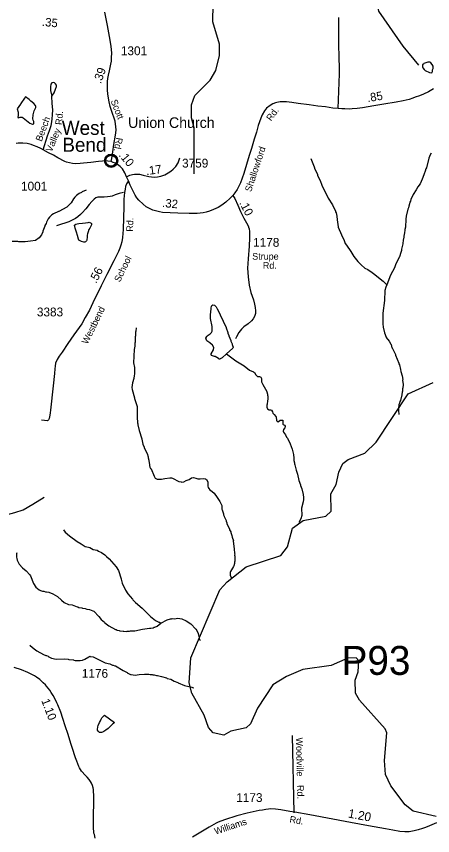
# Model space of a CAD drawing. Extents: x 1547597 to 1699558, y 810033 to 920809.
# Drawn here: x 1558854 to 1564751, y 847304 to 858918 of the extents above; entities that cross this region are included whole.
import ezdxf

# ---------------------------------------------------------------- set-up
doc = ezdxf.new("R2010")
doc.units = 0
for name, color, linetype in [('Exist Civil Demographics Community CELL', 7, 'Continuous'), ('Exist Civil Demographics Community Label', 7, 'Continuous'), ('Exist Cultural Church with Cemetery Label', 7, 'Continuous'), ('Exist Hydrographic Creek Single Shore', 7, 'Continuous'), ('Exist Hydrographic Misc Water Feature', 7, 'Continuous'), ('Exist Road Non-System Type 51', 7, 'Continuous'), ('Exist Road Non-System Type 51 Label', 7, 'Continuous'), ('Exist Road Secondary Mileage Hundredths English Label', 7, 'Continuous'), ('Exist Road Secondary Structure Pipe Number Label', 7, 'Continuous'), ('Exist Road Secondary Type 41 Attributed', 7, 'Continuous'), ('Exist Road Secondary Type 51 Attributed', 7, 'Continuous'), ('Exist Road Secondary Type 51 Label', 7, 'Continuous'), ('Exist Road Secondary Type 51 Number Label', 7, 'Continuous')]:
    doc.layers.add(name, color=color, linetype=linetype)

msp = doc.modelspace()

# ---------------------------------------------------------------- linework, layer by layer
at = {"layer": 'Exist Civil Demographics Community CELL'}
msp.add_lwpolyline([(1560119, 856884), (1560120, 856890), (1560121, 856896), (1560124, 856904), (1560127, 856909), (1560131, 856915), (1560134, 856920), (1560138, 856925), (1560143, 856929), (1560148, 856934), (1560154, 856937), (1560159, 856940), (1560164, 856943), (1560169, 856945), (1560175, 856947), (1560179, 856948), (1560184, 856949), (1560188, 856949), (1560195, 856950), (1560199, 856950), (1560205, 856949), (1560210, 856949), (1560214, 856948), (1560219, 856946), (1560225, 856944), (1560231, 856941), (1560237, 856938), (1560243, 856934), (1560248, 856930), (1560251, 856927), (1560255, 856923), (1560259, 856918), (1560262, 856913), (1560265, 856908), (1560268, 856903), (1560270, 856898), (1560271, 856893), (1560273, 856889), (1560274, 856883), (1560274, 856878), (1560275, 856872), (1560274, 856866), (1560274, 856860), (1560273, 856855), (1560271, 856849), (1560269, 856843), (1560267, 856838), (1560264, 856832), (1560261, 856827), (1560257, 856822), (1560253, 856817), (1560248, 856812), (1560243, 856808), (1560238, 856805), (1560233, 856802), (1560226, 856799), (1560219, 856796), (1560213, 856795), (1560207, 856793), (1560202, 856793), (1560198, 856793), (1560192, 856793), (1560188, 856793), (1560182, 856794), (1560176, 856795), (1560172, 856796), (1560167, 856798), (1560162, 856800), (1560158, 856803), (1560151, 856807), (1560146, 856811), (1560141, 856815), (1560136, 856820), (1560133, 856824), (1560130, 856828), (1560126, 856835), (1560124, 856839), (1560123, 856843), (1560120, 856851), (1560119, 856858), (1560118, 856863), (1560118, 856870), (1560118, 856874), (1560118, 856881)], close=True, dxfattribs=at)
for radius in [94.3, 76.7]:
    msp.add_circle((1560196, 856872), radius, dxfattribs=at)
at = {"layer": 'Exist Hydrographic Creek Single Shore'}
msp.add_lwpolyline([(1564801, 847575), (1564477, 847653), (1564361, 847741), (1564157, 848008), (1564084, 848170), (1564070, 848368), (1564101, 848761), (1564077, 848820), (1563716, 849225), (1563659, 849325), (1563653, 849509), (1563697, 849626), (1563707, 849783), (1563666, 849827), (1563549, 849819), (1563315, 849716), (1562914, 849661), (1562679, 849558), (1562485, 849444), (1562272, 849113), (1562169, 848889), (1562109, 848831), (1561892, 848783), (1561791, 848729), (1561642, 848761), (1561576, 848838), (1561512, 849014), (1561341, 849326), (1561302, 849468), (1561324, 849825), (1561738, 850788), (1561839, 850901), (1562109, 851116), (1562603, 851276), (1562697, 851399), (1562767, 851664), (1562919, 851772), (1563237, 851831), (1563313, 851905), (1563308, 852148), (1563385, 852281), (1563421, 852455), (1563481, 852578), (1563557, 852636), (1563792, 852726), (1563952, 852880), (1564404, 853567), (1564757, 853728)], dxfattribs=at)
at = {"layer": 'Exist Hydrographic Misc Water Feature'}
for points in [[(1561373, 856688), (1561374, 857338), (1561334, 857480), (1561337, 857664), (1561381, 857798), (1561601, 858016), (1561678, 858149), (1561731, 858365), (1561733, 858526), (1561638, 858843), (1561645, 859342), (1561700, 859725), (1561669, 859866), (1561472, 860081), (1561440, 860147), (1561443, 860354), (1561495, 860504), (1561382, 860782), (1561361, 861015), (1561375, 861432), (1561254, 861733), (1561273, 861900)], [(1564555, 858226), (1564334, 858496), (1563991, 858992), (1563920, 859286), (1563875, 859661), (1563811, 859787), (1563630, 859965), (1563107, 860156), (1562951, 860284), (1562788, 860543), (1562759, 860895), (1562694, 860995), (1562554, 861122), (1562347, 861225), (1562232, 861326), (1562091, 861388), (1561867, 861425), (1561701, 861501), (1561348, 861882), (1561273, 861900)], [(1564608, 858238), (1564608, 858204), (1564612, 858188), (1564630, 858164), (1564647, 858151), (1564707, 858123), (1564739, 858120), (1564751, 858138), (1564751, 858162), (1564760, 858178), (1564760, 858210), (1564746, 858234), (1564725, 858260), (1564713, 858269), (1564685, 858267), (1564653, 858259), (1564628, 858248), (1564622, 858240), (1564608, 858238)], [(1558917, 857682), (1558915, 857680), (1558911, 857672), (1558866, 857608), (1558877, 857560), (1558877, 857512), (1558873, 857488), (1558879, 857480), (1558909, 857488), (1558933, 857488), (1558948, 857479), (1559044, 857406), (1559067, 857394), (1559083, 857390), (1559091, 857390), (1559103, 857399), (1559100, 857429), (1559092, 857446), (1559088, 857468), (1559089, 857522), (1559104, 857577), (1559130, 857625), (1559130, 857641), (1559123, 857657), (1559099, 857683), (1559059, 857716), (1559035, 857740), (1558983, 857779), (1558968, 857757), (1558917, 857682)], [(1564733, 856979), (1564713, 856947), (1564709, 856931), (1564697, 856907), (1564663, 856772), (1564655, 856756), (1564646, 856724), (1564630, 856684), (1564628, 856673), (1564605, 856609), (1564576, 856545), (1564543, 856504), (1564519, 856458), (1564474, 856394), (1564442, 856323), (1564437, 856299), (1564429, 856283), (1564425, 856259), (1564413, 856227), (1564408, 856203), (1564400, 856187), (1564378, 856086), (1564370, 856044), (1564365, 855928), (1564357, 855896), (1564352, 855840), (1564348, 855832), (1564339, 855760), (1564335, 855752), (1564330, 855696), (1564309, 855617), (1564309, 855601), (1564299, 855573), (1564284, 855509), (1564279, 855505), (1564226, 855396), (1564210, 855354), (1564153, 855251), (1564101, 855114)], [(1563024, 856903), (1563075, 856784), (1563083, 856752), (1563118, 856679), (1563122, 856663), (1563159, 856591), (1563180, 856527), (1563270, 856342), (1563333, 856245), (1563376, 856156), (1563376, 856148), (1563384, 856132), (1563395, 856084), (1563398, 856036), (1563415, 855936), (1563413, 855932), (1563460, 855819), (1563496, 855739), (1563514, 855699), (1563530, 855675), (1563593, 855586), (1563636, 855513), (1563691, 855441), (1563739, 855394), (1563790, 855351), (1563834, 855330), (1563897, 855288), (1563913, 855272), (1564052, 855164), (1564101, 855114)], [(1559840, 856455), (1559784, 856429), (1559778, 856423), (1559744, 856406), (1559705, 856378), (1559681, 856355), (1559663, 856331), (1559628, 856275), (1559569, 856212), (1559457, 856154), (1559451, 856153), (1559378, 856121), (1559354, 856103), (1559322, 856071), (1559303, 856048), (1559279, 856000), (1559275, 855984), (1559258, 855952), (1559258, 855944), (1559229, 855873), (1559229, 855865), (1559207, 855819), (1559176, 855777), (1559124, 855742), (1559052, 855731), (1558976, 855724), (1558928, 855724), (1558912, 855721), (1558888, 855721), (1558872, 855725), (1558792, 855726)], [(1559739, 855981), (1559790, 855987), (1559834, 855992), (1559871, 855998), (1559883, 855999), (1559895, 855997), (1559913, 855987), (1559916, 855980), (1559916, 855962), (1559914, 855954), (1559906, 855942), (1559892, 855918), (1559882, 855895), (1559872, 855865), (1559863, 855836), (1559858, 855817), (1559857, 855794), (1559854, 855744), (1559849, 855735), (1559833, 855723), (1559822, 855719), (1559810, 855719), (1559775, 855728), (1559750, 855739), (1559739, 855747), (1559732, 855761), (1559719, 855813), (1559705, 855858), (1559687, 855915), (1559675, 855959), (1559696, 855971), (1559717, 855977), (1559739, 855981)], [(1564101, 855114), (1564087, 855080), (1564076, 855032), (1564069, 854888), (1564047, 854712), (1564044, 854673), (1564045, 854561), (1564050, 854513), (1564069, 854432), (1564095, 854370), (1564095, 854364), (1564134, 854316), (1564160, 854270), (1564165, 854267), (1564173, 854219), (1564179, 854217), (1564224, 854123), (1564224, 854115), (1564274, 854002), (1564274, 853994), (1564282, 853978), (1564297, 853914), (1564301, 853882), (1564320, 853821), (1564329, 853769), (1564327, 853761), (1564335, 853701), (1564330, 853649), (1564326, 853641), (1564325, 853601), (1564321, 853594), (1564317, 853554), (1564296, 853474), (1564288, 853458), (1564283, 853434), (1564275, 853418), (1564271, 853386), (1564267, 853378), (1564266, 853330), (1564273, 853276)], [(1561833, 854132), (1561768, 854079), (1561743, 854062), (1561735, 854060), (1561727, 854060), (1561716, 854070), (1561668, 854095), (1561660, 854095), (1561620, 854111), (1561612, 854123), (1561612, 854135), (1561647, 854191), (1561649, 854223), (1561632, 854255), (1561594, 854289), (1561553, 854320), (1561541, 854340), (1561539, 854356), (1561551, 854380), (1561557, 854388), (1561600, 854417), (1561620, 854439), (1561628, 854455), (1561630, 854479), (1561629, 854523), (1561602, 854635), (1561603, 854707), (1561607, 854715), (1561612, 854787), (1561616, 854803), (1561624, 854819), (1561636, 854829), (1561660, 854826), (1561682, 854802), (1561700, 854774), (1561731, 854710), (1561739, 854685), (1561825, 854509), (1561825, 854501), (1561848, 854436), (1561848, 854428), (1561863, 854396), (1561863, 854388), (1561890, 854324), (1561890, 854316), (1561910, 854276), (1561910, 854268), (1561918, 854251), (1561923, 854227), (1561921, 854213), (1561833, 854132)], [(1560549, 854505), (1560544, 854457), (1560540, 854443), (1560542, 854437), (1560540, 854389), (1560535, 854373), (1560535, 854301), (1560530, 854285), (1560530, 854245), (1560521, 854197), (1560511, 854005), (1560526, 853941), (1560529, 853865), (1560521, 853809), (1560517, 853801), (1560516, 853785), (1560500, 853721), (1560491, 853658), (1560495, 853628), (1560525, 853509), (1560529, 853503), (1560564, 853389), (1560563, 853335), (1560567, 853313), (1560565, 853201), (1560569, 853193), (1560569, 853153), (1560573, 853145), (1560573, 853129), (1560592, 853049), (1560630, 852928), (1560629, 852923), (1560643, 852856), (1560665, 852812), (1560665, 852804), (1560706, 852723), (1560723, 852675), (1560723, 852659), (1560731, 852627), (1560730, 852611), (1560734, 852603), (1560740, 852551), (1560745, 852527), (1560753, 852511), (1560763, 852502), (1560804, 852398), (1560822, 852373), (1560849, 852357), (1560910, 852359), (1560955, 852366), (1561028, 852377), (1561052, 852375), (1561067, 852371), (1561155, 852326), (1561187, 852321), (1561195, 852317), (1561227, 852321), (1561259, 852338), (1561304, 852355), (1561335, 852377), (1561365, 852380), (1561398, 852374), (1561426, 852364), (1561456, 852361), (1561504, 852365), (1561535, 852361), (1561547, 852353), (1561567, 852321), (1561566, 852259), (1561572, 852239), (1561580, 852225), (1561593, 852206), (1561627, 852184), (1561655, 852160), (1561700, 852099), (1561736, 852043), (1561763, 851986), (1561766, 851930), (1561771, 851923), (1561787, 851866), (1561789, 851850), (1561797, 851834), (1561797, 851826), (1561824, 851770), (1561824, 851762), (1561836, 851738), (1561836, 851730), (1561875, 851649), (1561875, 851641), (1561890, 851609), (1561890, 851601), (1561906, 851561), (1561909, 851537), (1561929, 851484), (1561927, 851477), (1561939, 851372), (1561938, 851364), (1561943, 851308), (1561947, 851300), (1561946, 851278)], [(1561833, 854132), (1561963, 854035), (1562080, 853966), (1562157, 853905), (1562211, 853880), (1562227, 853868), (1562245, 853837), (1562264, 853819), (1562272, 853815), (1562296, 853815), (1562318, 853803), (1562328, 853786), (1562328, 853739), (1562345, 853698), (1562402, 853602), (1562402, 853594), (1562413, 853561), (1562413, 853545), (1562417, 853537), (1562416, 853482), (1562412, 853474), (1562408, 853418), (1562404, 853410), (1562403, 853380), (1562409, 853362), (1562413, 853356), (1562435, 853341), (1562455, 853341), (1562469, 853335), (1562482, 853313), (1562486, 853291), (1562506, 853274), (1562530, 853248), (1562533, 853240), (1562539, 853188), (1562547, 853178), (1562561, 853172), (1562593, 853193), (1562629, 853195), (1562630, 853137), (1562636, 853131), (1562654, 853125), (1562664, 853111), (1562664, 853103), (1562656, 853087), (1562637, 853063), (1562635, 853039), (1562639, 853023), (1562666, 852987), (1562682, 852954), (1562694, 852938), (1562733, 852858), (1562760, 852785), (1562779, 852705), (1562783, 852653), (1562786, 852645), (1562786, 852621), (1562794, 852589), (1562794, 852573), (1562799, 852561), (1562817, 852485), (1562836, 852429), (1562855, 852340), (1562878, 852276), (1562878, 852268), (1562897, 852220), (1562916, 852140), (1562916, 852124), (1562920, 852116), (1562922, 852068), (1562919, 852036), (1562894, 851948), (1562897, 851844), (1562884, 851796), (1562856, 851742)], [(1559521, 851639), (1559547, 851608), (1559606, 851556), (1559713, 851474), (1559773, 851442), (1559828, 851403), (1559835, 851404), (1559896, 851390), (1559940, 851362), (1559996, 851349), (1560019, 851339), (1560059, 851316), (1560105, 851283), (1560129, 851259), (1560166, 851229), (1560265, 851116), (1560300, 851061), (1560339, 850945), (1560337, 850938), (1560350, 850881), (1560399, 850784), (1560432, 850734), (1560501, 850655), (1560505, 850647), (1560541, 850610), (1560634, 850529), (1560752, 850410), (1560824, 850355), (1560871, 850330), (1560883, 850328), (1560899, 850318)], [(1558859, 851315), (1558855, 851299), (1558855, 851253), (1558858, 851231), (1558866, 851207), (1558893, 851153), (1558941, 851100), (1558994, 851058), (1559046, 851001), (1559055, 850987), (1559098, 850880), (1559130, 850828), (1559177, 850787), (1559193, 850779), (1559225, 850771), (1559241, 850771), (1559265, 850762), (1559281, 850762), (1559313, 850754), (1559368, 850733), (1559434, 850692), (1559495, 850643), (1559531, 850611), (1559591, 850582), (1559646, 850574), (1559714, 850549), (1559722, 850549), (1559738, 850540), (1559782, 850532), (1559790, 850528), (1559830, 850523), (1559854, 850515), (1559890, 850511), (1559939, 850492), (1559953, 850484), (1560024, 850411), (1560056, 850368), (1560104, 850328), (1560106, 850322), (1560165, 850277), (1560258, 850226), (1560266, 850226), (1560282, 850218), (1560310, 850213), (1560318, 850209), (1560366, 850205), (1560374, 850201), (1560414, 850200), (1560422, 850204), (1560454, 850204), (1560470, 850207), (1560534, 850207), (1560642, 850229), (1560742, 850244), (1560758, 850244), (1560790, 850251), (1560807, 850259), (1560815, 850259), (1560847, 850275), (1560899, 850318)], [(1561946, 851278), (1561950, 851264), (1561949, 851192), (1561945, 851184), (1561945, 851160), (1561933, 851129), (1561932, 851121), (1561888, 851049), (1561883, 851033), (1561883, 850993), (1561900, 850959)], [(1560899, 850318), (1560988, 850361), (1561036, 850376), (1561052, 850376), (1561060, 850380), (1561092, 850379), (1561143, 850388), (1561200, 850378), (1561259, 850349), (1561325, 850305), (1561396, 850232), (1561410, 850212), (1561429, 850171), (1561445, 850107), (1561444, 850091), (1561448, 850083), (1561460, 850077)], [(1559044, 850003), (1559050, 850001), (1559107, 849951), (1559143, 849926), (1559238, 849873), (1559270, 849859), (1559278, 849859), (1559306, 849848), (1559306, 849842), (1559350, 849818), (1559419, 849804), (1559541, 849809), (1559589, 849807), (1559597, 849802), (1559661, 849794), (1559669, 849790), (1559685, 849789), (1559693, 849785), (1559749, 849785), (1559757, 849788), (1559789, 849792), (1559821, 849806), (1559878, 849841), (1559892, 849847), (1559898, 849843), (1559942, 849838), (1560113, 849756), (1560177, 849739), (1560216, 849723), (1560224, 849723), (1560248, 849710), (1560256, 849710), (1560367, 849643), (1560423, 849616), (1560423, 849612), (1560471, 849588), (1560478, 849589), (1560535, 849579), (1560594, 849588), (1560671, 849593), (1560691, 849591), (1560731, 849592), (1560747, 849588), (1560779, 849588), (1560787, 849584), (1560808, 849583), (1560838, 849575), (1560854, 849575), (1560910, 849558), (1560980, 849543), (1560990, 849533), (1561042, 849520), (1561089, 849496), (1561141, 849475), (1561147, 849470), (1561237, 849434), (1561340, 849409), (1561358, 849399), (1561370, 849404)], [(1560102, 849012), (1560242, 848908), (1560228, 848894), (1560216, 848883), (1560204, 848873), (1560177, 848846), (1560153, 848823), (1560120, 848797), (1560094, 848781), (1560075, 848771), (1560060, 848766), (1560044, 848764), (1560033, 848767), (1560020, 848776), (1560010, 848787), (1560005, 848797), (1560004, 848809), (1560006, 848846), (1560013, 848865), (1560033, 848909), (1560043, 848933), (1560055, 848956), (1560065, 848973), (1560078, 848989), (1560102, 849012)]]:
    msp.add_lwpolyline(points, dxfattribs=at)
at = {"layer": 'Exist Road Non-System Type 51'}
msp.add_line((1562788, 847628), (1562766, 848723), dxfattribs=at)
for points in [[(1563415, 857611), (1563430, 858104), (1563430, 858186), (1563428, 858340), (1563424, 858518), (1563424, 858904)], [(1559354, 857789), (1559389, 857836), (1559409, 857884), (1559420, 857922), (1559420, 857944), (1559410, 857964), (1559395, 857976), (1559381, 857980), (1559357, 857975), (1559342, 857959), (1559338, 857921), (1559339, 857867), (1559354, 857789)], [(1559235, 857024), (1559296, 857225), (1559323, 857299), (1559344, 857373), (1559357, 857421), (1559361, 857466), (1559366, 857522), (1559371, 857594), (1559360, 857681), (1559354, 857789)], [(1560371, 856421), (1560310, 856408), (1560254, 856387), (1560210, 856370), (1560180, 856364), (1560146, 856359), (1560095, 856355), (1560043, 856356), (1560009, 856355), (1559981, 856345), (1559957, 856327), (1559921, 856296), (1559884, 856250), (1559837, 856189), (1559784, 856134), (1559762, 856108), (1559725, 856075), (1559691, 856051), (1559634, 856024), (1559598, 856006), (1559542, 855987), (1559494, 855974), (1559423, 855949)], [(1562149, 855918), (1562152, 855909), (1562157, 855863), (1562158, 855779), (1562152, 855659), (1562136, 855483), (1562126, 855348), (1562138, 855225), (1562154, 855109), (1562177, 855002), (1562211, 854900), (1562228, 854836), (1562238, 854790), (1562243, 854746), (1562241, 854707), (1562226, 854664), (1562210, 854632), (1562187, 854602), (1562136, 854559), (1562078, 854516), (1562043, 854486), (1562004, 854435), (1561974, 854377), (1561959, 854348)], [(1559393, 853857), (1559374, 853682), (1559337, 853335), (1559332, 853297), (1559326, 853263), (1559316, 853218), (1559308, 853199), (1559294, 853186), (1559211, 853193)], [(1558475, 851891), (1558622, 851872), (1558726, 851858), (1558831, 851887), (1558950, 851925), (1559087, 852001), (1559249, 852100)]]:
    msp.add_lwpolyline(points, dxfattribs=at)
at = {"layer": 'Exist Road Secondary Type 41 Attributed'}
msp.add_lwpolyline([(1561922, 856381), (1561950, 856334), (1561991, 856242), (1562027, 856153), (1562076, 856059), (1562113, 855992), (1562137, 855950), (1562149, 855918)], dxfattribs=at)
at = {"layer": 'Exist Road Secondary Type 51 Attributed'}
for points in [[(1560196, 856859), (1560204, 856905), (1560220, 856999), (1560236, 857102), (1560258, 857233), (1560266, 857303), (1560264, 857356), (1560260, 857392), (1560253, 857432), (1560203, 857582), (1560184, 857642), (1560170, 857709), (1560151, 857817), (1560146, 857878), (1560143, 857959), (1560146, 857997), (1560150, 858038), (1560160, 858083), (1560173, 858146), (1560192, 858241), (1560199, 858281), (1560203, 858330), (1560205, 858401), (1560198, 858490), (1560184, 858580), (1560164, 858687), (1560143, 858788), (1560105, 858978)], [(1564766, 857891), (1564692, 857850), (1564620, 857815), (1564567, 857793), (1564506, 857771), (1564470, 857758), (1564417, 857741), (1564336, 857722), (1564234, 857704), (1564059, 857674), (1563919, 857649), (1563838, 857635), (1563758, 857622), (1563680, 857614), (1563613, 857607), (1563570, 857605), (1563509, 857606), (1563467, 857608), (1563415, 857611), (1563338, 857619), (1563233, 857634), (1563123, 857646), (1563004, 857663), (1562846, 857683), (1562755, 857695), (1562683, 857705), (1562631, 857707), (1562590, 857706), (1562546, 857698), (1562523, 857692), (1562487, 857677), (1562450, 857657), (1562397, 857615), (1562368, 857580), (1562335, 857521), (1562316, 857475), (1562281, 857372), (1562254, 857279), (1562223, 857178), (1562183, 857047), (1562152, 856944), (1562113, 856817), (1562074, 856693), (1562054, 856625), (1562028, 856559), (1562006, 856510), (1561980, 856464), (1561949, 856418), (1561922, 856381)], [(1560196, 856859), (1560151, 856867), (1560119, 856869), (1560073, 856867), (1560016, 856861), (1559910, 856848), (1559804, 856835), (1559759, 856831), (1559691, 856829), (1559649, 856833), (1559607, 856842), (1559565, 856853), (1559542, 856863), (1559439, 856913), (1559377, 856949), (1559308, 856986), (1559235, 857024), (1559199, 857043), (1559148, 857070), (1559098, 857090), (1559065, 857100), (1559006, 857116), (1558946, 857122), (1558910, 857123), (1558877, 857121), (1558848, 857116)], [(1560414, 856645), (1560388, 856702), (1560356, 856755), (1560322, 856792), (1560287, 856820), (1560257, 856837), (1560227, 856849), (1560196, 856859)], [(1560414, 856645), (1560459, 856669), (1560497, 856677), (1560529, 856680), (1560596, 856680), (1560649, 856669), (1560730, 856647), (1560806, 856641), (1560851, 856644), (1560899, 856653), (1560955, 856673), (1561004, 856698), (1561044, 856725), (1561076, 856753), (1561111, 856792), (1561145, 856842), (1561170, 856911)], [(1560440, 856588), (1560414, 856645)], [(1560440, 856588), (1560412, 856543), (1560399, 856508), (1560395, 856467), (1560386, 856420), (1560378, 856326), (1560376, 856220), (1560372, 856060), (1560367, 855898), (1560356, 855785), (1560347, 855724), (1560335, 855677), (1560320, 855630), (1560300, 855585), (1560232, 855454), (1560137, 855259), (1560054, 855097), (1559937, 854855), (1559888, 854752), (1559829, 854649), (1559779, 854561), (1559668, 854403), (1559584, 854279), (1559500, 854156), (1559461, 854102), (1559430, 854053), (1559409, 854004), (1559403, 853958), (1559396, 853920), (1559393, 853857)], [(1561922, 856381), (1561883, 856340), (1561823, 856284), (1561763, 856242), (1561715, 856211), (1561647, 856179), (1561591, 856158), (1561544, 856143), (1561498, 856133), (1561415, 856122), (1561300, 856123), (1561141, 856130), (1560925, 856140), (1560883, 856147), (1560827, 856161), (1560789, 856172), (1560748, 856191), (1560694, 856219), (1560650, 856254), (1560587, 856314), (1560560, 856348), (1560536, 856385), (1560507, 856439), (1560485, 856487), (1560467, 856527), (1560440, 856588)], [(1559972, 847270), (1559959, 847318), (1559953, 847340), (1559949, 847366), (1559945, 847402), (1559946, 847564), (1559948, 847633), (1559950, 847729), (1559951, 847814), (1559951, 847882), (1559948, 847926), (1559945, 847956), (1559940, 847984), (1559932, 848016), (1559918, 848049), (1559905, 848073), (1559885, 848100), (1559857, 848131), (1559831, 848157), (1559777, 848218), (1559760, 848243), (1559748, 848265), (1559739, 848286), (1559710, 848359), (1559692, 848405), (1559643, 848552), (1559625, 848611), (1559585, 848740), (1559547, 848860), (1559512, 848966), (1559482, 849053), (1559440, 849158), (1559427, 849188), (1559395, 849256), (1559374, 849292), (1559348, 849334), (1559326, 849364), (1559280, 849424), (1559264, 849442), (1559235, 849472), (1559206, 849500), (1559184, 849517), (1559139, 849550), (1559109, 849570), (1559015, 849618), (1558926, 849655), (1558820, 849689)], [(1564807, 847487), (1564706, 847441), (1564649, 847420), (1564609, 847405), (1564545, 847384), (1564488, 847371), (1564419, 847360), (1564358, 847360), (1564285, 847363), (1564189, 847383), (1564083, 847401), (1563842, 847444), (1563588, 847491), (1563012, 847597), (1562801, 847636), (1562726, 847648), (1562603, 847670), (1562526, 847679), (1562451, 847682), (1562424, 847680), (1562386, 847675), (1562340, 847666), (1562293, 847660), (1562125, 847622), (1561975, 847586), (1561801, 847529), (1561715, 847494), (1561686, 847480), (1561585, 847425), (1561350, 847283)]]:
    msp.add_lwpolyline(points, dxfattribs=at)

# ---------------------------------------------------------------- texts
at = {"layer": 'Exist Civil Demographics Community Label'}
for s, p in [('West', (1559497, 857238)), ('Bend', (1559505, 856998))]:
    msp.add_text(s, height=200, dxfattribs=at).set_placement(p)
at = {"layer": 'Exist Cultural Church with Cemetery Label'}
msp.add_text('Union Church', height=150, dxfattribs=at).set_placement((1560436, 857337))
at = {"layer": 'Exist Road Non-System Type 51 Label'}
for s, rotation, p in [('Rd.', 84.8979, (1559498, 857376)), ('Beech', 69.8107, (1559211, 857137)), ('Valley', 67.6977, (1559354, 856987)), ('Woodville', 271.1564, (1562816, 848694)), ('Rd.', 271.1564, (1562830, 848020))]:
    msp.add_text(s, height=95, rotation=rotation, dxfattribs=at).set_placement(p)
at = {"layer": 'Exist Road Secondary Mileage Hundredths English Label'}
for s, height, rotation, p in [('.35', 120, 354.2051, (1559212, 858784)), ('.39', 120, 69.6679, (1560050, 857956)), ('.85', 120, 9.4455, (1563833, 857702)), ('.10', 120, 309.2747, (1560298, 856948)), ('.17', 120, 7.4353, (1560697, 856668)), ('.32', 120, 354.9159, (1560916, 856216)), ('.10', 120, 297.1904, (1562008, 856275)), ('.56', 120, 62.607, (1559983, 855125)), ('1.10', 120, 290.941, (1559204, 849219)), ('1.20', 125, 349.4226, (1563547, 847562))]:
    msp.add_text(s, height=height, rotation=rotation, dxfattribs=at).set_placement(p)
at = {"layer": 'Exist Road Secondary Structure Pipe Number Label'}
msp.add_text('P93', height=410.1, dxfattribs=at).set_placement((1563461, 849583))
at = {"layer": 'Exist Road Secondary Type 51 Label'}
for s, rotation, p in [('Scott', 291.0461, (1560188, 857719)), ('Rd.', 54.0884, (1562463, 857426)), ('Rd.', 259.856, (1560269, 857206)), ('Shallowford', 71.7625, (1562179, 856423)), ('Rd.', 88.4633, (1560506, 855865)), ('School', 64.2226, (1560320, 855143)), ('Westbend', 63.9267, (1559861, 854262)), ('Rd.', 350.5716, (1562719, 847491)), ('Williams', 18.2085, (1561677, 847317))]:
    msp.add_text(s, height=95, rotation=rotation, dxfattribs=at).set_placement(p)
for s, p in [('Strupe', (1562195, 855469)), ('Rd.', (1562346, 855340))]:
    msp.add_text(s, height=95, dxfattribs=at).set_placement(p)
at = {"layer": 'Exist Road Secondary Type 51 Number Label'}
for s, p in [('1301', (1560334, 858368)), ('3759', (1561201, 856775)), ('1001', (1558919, 856449)), ('1178', (1562208, 855652)), ('3383', (1559144, 854665)), ('1176', (1559781, 849542)), ('1173', (1561969, 847781))]:
    msp.add_text(s, height=125, dxfattribs=at).set_placement(p)

doc.saveas('drawing.dxf')
